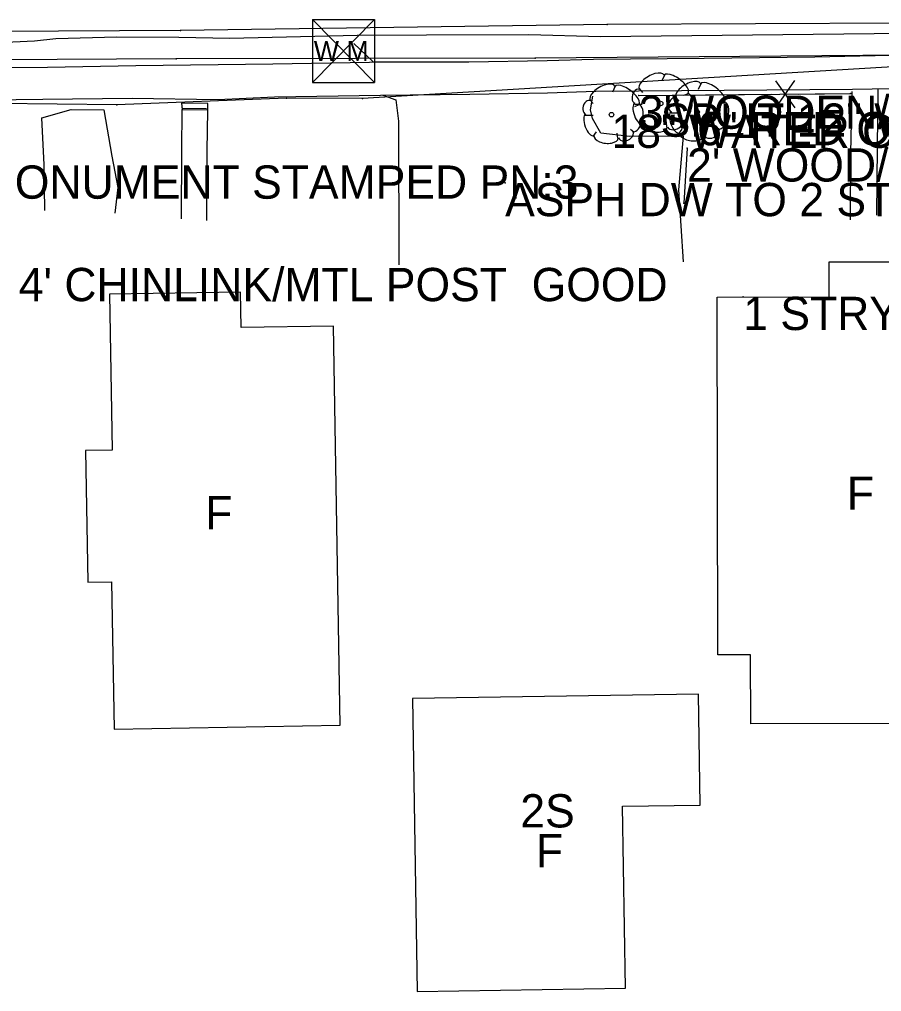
# Model space of a CAD drawing. Extents: x 1304270 to 1306561, y 1876019 to 1876752.
# Drawn here: x 1306055.3 to 1306184.9, y 1876252.4 to 1876398.5 of the extents above; entities that cross this region are included whole.
import ezdxf

# ---------------------------------------------------------------- set-up
doc = ezdxf.new("R2010")
doc.units = 0
for name, color, linetype in [('S_BUILDING', 7, 'Continuous'), ('S_BUILDING_ANNOT', 7, 'Continuous'), ('S_DRIVEWAY', 7, 'Continuous'), ('S_EDGE_CONCRETE', 7, 'Continuous'), ('S_EDGE_PAVEMENT', 7, 'Continuous'), ('S_FENCE', 7, 'Continuous'), ('S_FENCE_ANNOT', 7, 'Continuous'), ('S_FIBER_OPTIC_CABLE', 7, 'Continuous'), ('S_GAS_UTILITIES', 7, 'Continuous'), ('S_MSC_PT_SYM', 7, 'Continuous'), ('S_PRIMARY_CTL_ANNOT', 7, 'Continuous'), ('S_SIDEWALK', 7, 'Continuous'), ('S_STR_PT_SYM', 7, 'Continuous'), ('S_SURVEY_TEXT_ANNOT', 7, 'Continuous'), ('S_TREE', 7, 'Continuous'), ('S_TREE_ANNOT', 7, 'Continuous'), ('S_UTL_PT_SYM', 7, 'Continuous'), ('S_WATER_UTILITIES', 7, 'Continuous')]:
    doc.layers.add(name, color=color, linetype=linetype)

msp = doc.modelspace()

# ---------------------------------------------------------------- linework, layer by layer
at = {"layer": 'S_BUILDING'}
for points in [[(1306160.27, 1876302.99), (1306160.13, 1876356.76), (1306176.97, 1876356.8), (1306176.96, 1876362.05), (1306187.16, 1876362.08), (1306187.17, 1876357.43), (1306202.04, 1876357.47), (1306202.18, 1876304.76), (1306194.65, 1876304.74), (1306194.68, 1876292.7), (1306165.2, 1876292.62), (1306165.17, 1876303)], [(1306103.5, 1876292.42), (1306102.49, 1876352.41), (1306088.61, 1876352.18), (1306088.52, 1876357.51), (1306068.84, 1876357.18), (1306069.23, 1876333.77), (1306065.25, 1876333.7), (1306065.59, 1876313.91), (1306069.15, 1876313.97), (1306069.53, 1876291.84)], [(1306114.38, 1876296.42), (1306115.08, 1876252.39), (1306146.37, 1876252.88), (1306145.94, 1876280.24), (1306157.6, 1876280.42), (1306157.34, 1876297.1)]]:
    msp.add_lwpolyline(points, close=True, dxfattribs=at)
at = {"layer": 'S_DRIVEWAY'}
for points in [[(1306105.58, 1876394.89), (1306108.35, 1876392.21), (1306108.39, 1876392.22)], [(1306109.92, 1876387.09), (1306111.86, 1876386.4), (1306112.26, 1876383.22), (1306112.3, 1876361.59)], [(1306155.12, 1876362.04), (1306154.41, 1876372.89), (1306155.08, 1876380.96), (1306147.01, 1876380.89), (1306142.69, 1876381.39), (1306141.43, 1876383.6), (1306141.1, 1876384.92), (1306141.47, 1876386.96)], [(1306059.11, 1876369.8), (1306059.04, 1876376.65), (1306058.69, 1876383.71), (1306063.09, 1876384.94), (1306068, 1876384.91), (1306069.21, 1876377.95), (1306070.11, 1876373.23), (1306069.65, 1876369.37)]]:
    msp.add_lwpolyline(points, dxfattribs=at)
at = {"layer": 'S_EDGE_CONCRETE'}
for points in [[(1306180.17, 1876368.37), (1306180.23, 1876378.4), (1306180.43, 1876387.68)], [(1306184.28, 1876387.97), (1306184.21, 1876379.4), (1306184.1, 1876369.06)], [(1306079.68, 1876385.92), (1306079.76, 1876384.96), (1306079.73, 1876384.92), (1306079.66, 1876378.8), (1306079.59, 1876368.54)], [(1306083.63, 1876385.87), (1306079.68, 1876385.92)], [(1306083.49, 1876368.25), (1306083.52, 1876378.82), (1306083.6, 1876384.77), (1306083.63, 1876384.94), (1306083.63, 1876385.87)], [(1306079.84, 1876385.16), (1306083.4, 1876385.13)], [(1306083.52, 1876384.86), (1306079.85, 1876384.91)]]:
    msp.add_lwpolyline(points, dxfattribs=at)
at = {"layer": 'S_EDGE_PAVEMENT'}
msp.add_lwpolyline([(1306045.6, 1876394.73), (1306057.59, 1876395.26), (1306060.8, 1876395.61), (1306069.96, 1876395.9), (1306079.27, 1876395.83), (1306086.92, 1876395.7), (1306106.08, 1876396.12), (1306116.48, 1876396.17), (1306131.84, 1876396.21), (1306142.64, 1876395.95), (1306165.48, 1876396.19), (1306188.31, 1876396.43)], dxfattribs=at)
at = {"layer": 'S_FENCE'}
for p, q in [((1306168.94, 1876389.29), (1306171.84, 1876385.22)), ((1306168.94, 1876389.29), (1306171.84, 1876385.22)), ((1306168.97, 1876385.2), (1306171.8, 1876389.32)), ((1306168.97, 1876385.2), (1306171.8, 1876389.32)), ((1306148.39, 1876387.06), (1306180.21, 1876387.34)), ((1306155.64, 1876379.13), (1306155.13, 1876370.87))]:
    msp.add_line(p, q, dxfattribs=at)
for points in [[(1306172.39, 1876387.27), (1306180.21, 1876387.34)], [(1306172.39, 1876387.27), (1306180.21, 1876387.34)], [(1306148.39, 1876387.06), (1306168.39, 1876387.24)], [(1306148.39, 1876387.06), (1306168.39, 1876387.24)], [(1306155.64, 1876379.13), (1306155.13, 1876370.87)], [(1306155.64, 1876379.13), (1306155.13, 1876370.87)]]:
    msp.add_lwpolyline(points, dxfattribs=at)
at = {"layer": 'S_FIBER_OPTIC_CABLE'}
for p, q in [((1306143.62, 1876397.73), (1306079.49, 1876396.85)), ((1306202.59, 1876398), (1306143.62, 1876397.73)), ((1306079.49, 1876396.85), (1306046.09, 1876396.66)), ((1306248.72, 1876395.07), (1306106.88, 1876386.6)), ((1306069.93, 1876385.68), (1306046.82, 1876385.94)), ((1306095.42, 1876386.67), (1306069.93, 1876385.68)), ((1306106.88, 1876386.6), (1306095.42, 1876386.67))]:
    msp.add_line(p, q, dxfattribs=at)
at = {"layer": 'S_GAS_UTILITIES'}
for p, q in [((1306078.88, 1876392.59), (1306048.03, 1876392.4)), ((1306132.81, 1876392.65), (1306078.88, 1876392.59)), ((1306193.15, 1876393.15), (1306132.81, 1876392.65))]:
    msp.add_line(p, q, dxfattribs=at)
at = {"layer": 'S_MSC_PT_SYM'}
for points in [[(1306180.21, 1876387.34), (1306180.21, 1876387.39), (1306180.21, 1876387.34), (1306180.16, 1876387.34), (1306180.21, 1876387.34), (1306180.21, 1876387.29), (1306180.21, 1876387.34), (1306180.26, 1876387.34)], [(1306148.39, 1876387.06), (1306148.39, 1876387.11), (1306148.39, 1876387.06), (1306148.34, 1876387.06), (1306148.39, 1876387.06), (1306148.39, 1876387.01), (1306148.39, 1876387.06), (1306148.44, 1876387.06)], [(1306155.64, 1876379.13), (1306155.64, 1876379.18), (1306155.64, 1876379.13), (1306155.59, 1876379.13), (1306155.64, 1876379.13), (1306155.64, 1876379.08), (1306155.64, 1876379.13), (1306155.69, 1876379.13)], [(1306128.29, 1876373.92), (1306128.29, 1876373.97), (1306128.29, 1876373.92), (1306128.24, 1876373.92), (1306128.29, 1876373.92), (1306128.29, 1876373.87), (1306128.29, 1876373.92), (1306128.34, 1876373.92)], [(1306155.13, 1876370.87), (1306155.13, 1876370.92), (1306155.13, 1876370.87), (1306155.08, 1876370.87), (1306155.13, 1876370.87), (1306155.13, 1876370.82), (1306155.13, 1876370.87), (1306155.18, 1876370.87)]]:
    msp.add_lwpolyline(points, dxfattribs=at)
at = {"layer": 'S_SIDEWALK'}
for points in [[(1305952.26, 1876390.24), (1305960.41, 1876390.32), (1305966.26, 1876390.42), (1305977.98, 1876390.44), (1306001.88, 1876390.73), (1306025.78, 1876391.03), (1306046.11, 1876391.23), (1306059.51, 1876391.31), (1306072.82, 1876391.56), (1306093.38, 1876391.82), (1306107.91, 1876392.05), (1306108.42, 1876392.1), (1306122.83, 1876392.12), (1306134.63, 1876392.34), (1306141.58, 1876392.5), (1306158.19, 1876392.68), (1306174.81, 1876392.86), (1306188.4, 1876393.18)], [(1305946.19, 1876385.43), (1305960.07, 1876385.78), (1305966.36, 1876385.64), (1305978.22, 1876385.78), (1305997.78, 1876385.93), (1306001.65, 1876386), (1306023.78, 1876386.14), (1306028.37, 1876386.22), (1306037.11, 1876386.23), (1306046.79, 1876386.36), (1306058.81, 1876386.53), (1306072.25, 1876386.67), (1306085.1, 1876386.45), (1306093.62, 1876386.85), (1306109.56, 1876387.13), (1306122.97, 1876387.27), (1306134.64, 1876387.44), (1306141.92, 1876387.73), (1306161.2, 1876387.87), (1306180.48, 1876388.02), (1306189.34, 1876388.14)]]:
    msp.add_lwpolyline(points, dxfattribs=at)
at = {"layer": 'S_STR_PT_SYM'}
msp.add_lwpolyline([(1306164.07, 1876356.81), (1306164.07, 1876356.86), (1306164.07, 1876356.81), (1306164.02, 1876356.81), (1306164.07, 1876356.81), (1306164.07, 1876356.76), (1306164.07, 1876356.81), (1306164.12, 1876356.81)], dxfattribs=at)
at = {"layer": 'S_TREE'}
for p, q in [((1306152.22, 1876390.11), (1306151.83, 1876389.25)), ((1306157.7, 1876388.82), (1306157.32, 1876387.97)), ((1306144.83, 1876388.44), (1306144.44, 1876387.58)), ((1306148.42, 1876388.09), (1306148.92, 1876387.51)), ((1306141.03, 1876386.42), (1306141.54, 1876385.84)), ((1306153.91, 1876386.81), (1306154.41, 1876386.23)), ((1306155.78, 1876387.32), (1306155.12, 1876387.05)), ((1306161.27, 1876386.03), (1306160.61, 1876385.76)), ((1306148.39, 1876385.65), (1306147.74, 1876385.38)), ((1306147.76, 1876385.77), (1306148.89, 1876385.77)), ((1306153.25, 1876384.48), (1306154.37, 1876384.48)), ((1306140.37, 1876384.1), (1306141.5, 1876384.1)), ((1306148.92, 1876382.59), (1306149.39, 1876383.29)), ((1306152.61, 1876382.32), (1306152.53, 1876383.09)), ((1306155.01, 1876383.21), (1306154.54, 1876383.64)), ((1306141.54, 1876380.92), (1306142, 1876381.62)), ((1306147.62, 1876381.54), (1306147.15, 1876381.97)), ((1306154.41, 1876381.31), (1306154.88, 1876382)), ((1306158.09, 1876381.03), (1306158.01, 1876381.81)), ((1306160.49, 1876381.93), (1306160.03, 1876382.35)), ((1306145.22, 1876380.65), (1306145.14, 1876381.42))]:
    msp.add_line(p, q, dxfattribs=at)
for centre in [(1306151.66, 1876385.86), (1306144.27, 1876384.19), (1306157.15, 1876384.58)]:
    msp.add_circle(centre, 0.341, dxfattribs=at)
for centre, major_axis, ratio, start_param, end_param in [((1306150.32, 1876389.06), (1.86, 1.08), 0.471018, 0, 3.141593), ((1306153.98, 1876388.74), (-1.81, 1.36), 0.405113, 3.141593, 6.283186), ((1306142.94, 1876387.39), (1.86, 1.08), 0.471018, 0, 3.141593), ((1306146.59, 1876387.07), (-1.81, 1.36), 0.405113, 3.141593, 6.283186), ((1306155.81, 1876387.78), (1.86, 1.08), 0.471018, 0, 3.141593), ((1306159.47, 1876387.46), (-1.81, 1.36), 0.405113, 3.141593, 6.283186), ((1306148.09, 1876386.95), (0.31, 1.03), 0.646762, 0, 3.141593), ((1306155.33, 1876385.33), (0.46, 2.04), 0.482994, 3.141593, 6.283185), ((1306140.7, 1876385.28), (0.31, 1.03), 0.646762, 0, 3.141593), ((1306148.39, 1876384.3), (-0.61, 1.6), 0.420543, 6.283185, 9.424777), ((1306153.58, 1876385.67), (0.31, 1.03), 0.646762, 0, 3.141593), ((1306160.82, 1876384.05), (0.46, 2.04), 0.482994, 3.141593, 6.283185), ((1306147.95, 1876383.66), (0.46, 2.04), 0.482994, 3.141593, 6.283185), ((1306153.88, 1876383.02), (-0.61, 1.6), 0.420543, 6.283185, 9.424777), ((1306141.01, 1876382.63), (-0.61, 1.6), 0.420543, 6.283185, 9.424777), ((1306153.81, 1876382.81), (1.09, 0.46), 0.711534, 3.141592, 6.283185), ((1306146.42, 1876381.14), (1.09, 0.46), 0.711534, 3.141592, 6.283185), ((1306150.85, 1876382.52), (-1.83, 0.19), 0.529943, 0, 3.141593), ((1306159.3, 1876381.53), (1.09, 0.46), 0.711534, 3.141592, 6.283185), ((1306143.47, 1876380.85), (-1.83, 0.19), 0.529943, 0, 3.141593), ((1306156.34, 1876381.23), (-1.83, 0.19), 0.529943, 0, 3.141593)]:
    msp.add_ellipse(centre, major_axis=major_axis, ratio=ratio, start_param=start_param, end_param=end_param, dxfattribs=at)
at = {"layer": 'S_UTL_PT_SYM'}
for points in [[(1306143.62, 1876397.73), (1306143.62, 1876397.78), (1306143.62, 1876397.73), (1306143.57, 1876397.73), (1306143.62, 1876397.73), (1306143.62, 1876397.68), (1306143.62, 1876397.73), (1306143.67, 1876397.73)], [(1306079.49, 1876396.85), (1306079.49, 1876396.9), (1306079.49, 1876396.85), (1306079.44, 1876396.85), (1306079.49, 1876396.85), (1306079.49, 1876396.8), (1306079.49, 1876396.85), (1306079.54, 1876396.85)], [(1306078.88, 1876392.59), (1306078.88, 1876392.64), (1306078.88, 1876392.59), (1306078.83, 1876392.59), (1306078.88, 1876392.59), (1306078.88, 1876392.54), (1306078.88, 1876392.59), (1306078.93, 1876392.59)], [(1306132.81, 1876392.65), (1306132.81, 1876392.7), (1306132.81, 1876392.65), (1306132.76, 1876392.65), (1306132.81, 1876392.65), (1306132.81, 1876392.6), (1306132.81, 1876392.65), (1306132.86, 1876392.65)], [(1306095.42, 1876386.67), (1306095.42, 1876386.72), (1306095.42, 1876386.67), (1306095.37, 1876386.67), (1306095.42, 1876386.67), (1306095.42, 1876386.62), (1306095.42, 1876386.67), (1306095.47, 1876386.67)], [(1306106.88, 1876386.6), (1306106.88, 1876386.65), (1306106.88, 1876386.6), (1306106.83, 1876386.6), (1306106.88, 1876386.6), (1306106.88, 1876386.55), (1306106.88, 1876386.6), (1306106.93, 1876386.6)], [(1306069.93, 1876385.68), (1306069.93, 1876385.73), (1306069.93, 1876385.68), (1306069.88, 1876385.68), (1306069.93, 1876385.68), (1306069.93, 1876385.63), (1306069.93, 1876385.68), (1306069.98, 1876385.68)]]:
    msp.add_lwpolyline(points, dxfattribs=at)
at = {"layer": 'S_WATER_UTILITIES'}
for p, q in [((1306099.34, 1876398.49), (1306108.68, 1876398.49)), ((1306099.34, 1876398.49), (1306099.34, 1876389)), ((1306099.34, 1876398.49), (1306108.68, 1876389)), ((1306108.68, 1876398.49), (1306099.34, 1876389)), ((1306108.68, 1876398.49), (1306108.68, 1876389)), ((1306099.34, 1876389), (1306108.68, 1876389))]:
    msp.add_line(p, q, dxfattribs=at)

# ---------------------------------------------------------------- texts
at = {"layer": 'S_BUILDING_ANNOT'}
for s, p in [('1 STRY WOOD', (1306164.07, 1876351.81)), ('F', (1306179.63, 1876324.79)), ('F', (1306083.23, 1876321.85)), ('2S', (1306130.57, 1876277.05)), ('F', (1306132.91, 1876271.05))]:
    msp.add_text(s, height=5, dxfattribs=at).set_placement(p)
at = {"layer": 'S_FENCE_ANNOT'}
for s, p in [("3'WOODEN/ WOODEN POST  POOR", (1306148.39, 1876382.06)), ("2' WOOD/WOOD POST POOR", (1306155.64, 1876374.13)), ("4' CHINLINK/MTL POST  GOOD", (1306055.21, 1876356.15))]:
    msp.add_text(s, height=5, dxfattribs=at).set_placement(p)
at = {"layer": 'S_PRIMARY_CTL_ANNOT'}
msp.add_text('PD:AHTD STD. MONUMENT STAMPED PN:3', height=5, dxfattribs=at).set_placement((1306000.75, 1876371.55))
at = {"layer": 'S_SURVEY_TEXT_ANNOT'}
msp.add_text('ASPH DW TO 2 STRY BU', height=5, dxfattribs=at).set_placement((1306128.29, 1876368.92))
at = {"layer": 'S_TREE_ANNOT'}
for s, p in [('SPLIT 12" WATER OAK', (1306151.66, 1876380.86)), ('6" RED OAK', (1306157.15, 1876379.58)), ('18" WATER OAK', (1306144.27, 1876379.19))]:
    msp.add_text(s, height=5, dxfattribs=at).set_placement(p)
at = {"layer": 'S_WATER_UTILITIES'}
msp.add_text('W M', height=3, rotation=360, dxfattribs=at).set_placement((1306099.54, 1876392.26))

doc.saveas('drawing.dxf')
